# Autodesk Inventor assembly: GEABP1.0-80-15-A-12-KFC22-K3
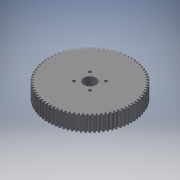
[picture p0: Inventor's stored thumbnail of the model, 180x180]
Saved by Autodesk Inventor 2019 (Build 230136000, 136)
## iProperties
Category: PARTsolutions
Company: MISUMI
Created: 2022-11
Part Number: GEABP1.0-80-15-A-12-KFC22-K3
Catalog Web Link: www.cadenas.de
Description: GEABM, GEABMS, GEABMT, GEABP, GEABPS, GEABPT, GEABA, GEABAS, GEABAT-Plastic Spur Gears - Pressure Angle 20 Degrees, Module 0.5/0.8/1.0/1.5/2.0/2.5/3.0
Vendor: MISUMI
Document SubType Name: Assembly
Designer: psAdmin
Manufacturer: MISUMI
Mass: 72.9245 g
Surface Area: 182.111 cm^2
Volume: 72.9245 cm^3
Density: 1 g/cm^3
Title: GEABP1.0-80-15-A-12-KFC22-K3
Author: Cadenas PARTsolutions
Comments: Plastic Spur Gears - Pressure Angle 20 Degrees, Module 0.5/0.8/1.0/1.5/2.0/2.5/3.0
PSOL_IDENT_0: {$CADENAS_DATA/23d-libs/misumi/metric/54_spur_gears/geabms20_asmtab.prj},415 {VTYP=3D},{STYP=ASSTAB}
PSOL_IDENT_1: ,{NB=GEABP1.0-80-15-A-12-KFC22-K3},{LINA=GEABP1.0-80-15-A-12-KFC22-K3},{NN=GEABM, GEABMS, GEABMT, GE
PSOL_IDENT_2: ABP, GEABPS, GEABPT, GEABA, GEABAS, GEABAT},{DATE=16.08.2021 10:08:31},{GEOMDATE=16.08.2021 10:08:28
PSOL_IDENT_3: },{VERSION=},{LINEID=30},{WBVAR=MATSG,MATCR,NT,B,TS,PS,ALT1,ALT2,TPC,ALT11,ALT10,BS,ALT3,Z,J,ALT4,Q,
PSOL_IDENT_4: R,S,T,ALT5,LFC,LTC,MALT5,ALT6,KFC,KTC,K},{WBNUMERIC=NT,B,BS,Z,J,Q,R,S,T,LFC,LTC,KFC,KTC,K}  {NB=GEAB
PSOL_IDENT_5: P1.0-80-15-A-12-KFC22-K3},{LINA=GEABP1.0-80-15-A-12-KFC22-K3},{KT=DUMMY},{PN=GEABP1.0-80-15-A-12-KFC
PSOL_IDENT_6: 22-K3},{TYPE=GEABP},{MATSG=PW},{MATSGALG='MCN','MC Nylon','PW','Polyacetal White','PB','Polyacetal B
PSOL_IDENT_7: lue'},{MATCR=},{MATCRALG='','-','S45C','1045 Carbon Steel','SUS304','304 Stainless Steel'},{MOD=1.0}
PSOL_IDENT_8: ,{MOD1=1.0},{NT=80},{NTALG=15,16,18,20,22,24,25,26,28,30,32,35,36,40,45,48,50,55,60,70,75,80,90,100,
PSOL_IDENT_9: 120},{B=15},{BALG=10,15},{TS=A},{TSALG='A','A','B','B'},{TSPN=-A},{PS=12},{PSALG='10','10','11','11'
PSOL_IDENT_10: ,'12','12','13','13','14','14','15','15','16','16','17','17','18','18','19','19','20','20','21','21'
PSOL_IDENT_11: ,'22','22','23','23','24','24','25','25','26','26','27','27','28','28'},{PSCRL='10','10','11','11','
PSOL_IDENT_12: 12','12','13','13','14','14','15','15','16','16','17','17','18','18','19','19','20','20','21','21','
PSOL_IDENT_13: 22','22','23','23','24','24','25','25','26','26','27','27','28','28'},{PSCRW='10','10','12','12','15'
PSOL_IDENT_14: ,'15','20','20'},{DD=80.0},{DD05=40},{DD08=64},{DD10=80},{DD15=120},{DD20=0},{DD25=0},{DD30=0},{D=82
PSOL_IDENT_15: .0},{D05=41},{D08=65.6},{D10=82},{D15=123},{D20=0},{D25=0},{D30=0},{G=77.50},{G05=38.75},{G08=62},{G
PSOL_IDENT_16: 10=77.5},{G15=116.25},{G20=0},{G25=0},{G30=0},{H=0.0},{L=0},{LL1=0},{LL2=0.0},{M=-},{M3D=0},{P=12.00
PSOL_IDENT_17: },{DD1=0},{CIFR=15},{CIFM=0},{CIFK=0},{CIFTAP=0},{SCREW=0.000},{SCREWL=0.000},{ALT1=},{ALT1ALG='','N
PSOL_IDENT_18: ot applicable'},{ALT1PN=},{ALT2=},{ALT2ALG='','Not applicable'},{TPC=N/A},{TPCALG='N/A'},{ALT2PN=},{
PSOL_IDENT_19: KC=0},{ALT11=},{ALT11ALG='','Not applicable'},{ALT11PN=},{DEG=0},{ALT10=},{ALT10ALG= '','Not applica
PSOL_IDENT_20: ble' },{ALT10PN=},{BS=0.0},{BSALG=0},{BSMIN=3.000},{BSMINALG=3},{BSMAX=0},{LL13D=0},{LL23D=0},{ALT3=
PSOL_IDENT_21: },{ALT3ALG= '','w/o Stepped Hole','DHL','with DHL (Stepped Hole)','DHR','with DHR (Stepped Hole)' },
PSOL_IDENT_22: {ALT3PN=},{ZJPN=},{ALT31=1},{ALT32=1},{Z=0},{ZALG=0},{ZMINL=14},{ZMAXL=73},{ZMINR=14},{ZMAXR=73},{ZP
PSOL_IDENT_23: N=},{J=0.0},{JALG=0},{JMIN=2},{JMAX=0},{JPN=},{ALT4=},{ALT4ALG= '','w/o WDH (Both Ends Stepped Hole)'
PSOL_IDENT_24: ,'WDH','with WDH (Both Ends Stepped Hole)' },{ALT4PN=},{QRSTPN=},{LB=15.000},{Q=0},{QALG=0},{QMIN=14
PSOL_IDENT_25: },{QMAX=73},{QPN=},{R=0},{RALG=0},{RMIN=14},{RMAX=73},{RPN=},{S=0},{SALG=0},{SMIN=3},{SMAX=9},{SPN=}
PSOL_IDENT_26: ,{T=0},{TALG=0},{TMIN=3},{TMAX=0},{TPN=},{ALT5=},{ALT5ALG= '','w/o Side Slotted Hole','LFC','with LF
PSOL_IDENT_27: C (Side Slotted Hole)','LTC','with LTC (Side Slotted Hole)' },{LFC=0},{LFCALG=0},{LTC=0},{LTCALG=0},
PSOL_IDENT_28: {LPCDMIN=20},{LPCDMAX=70},{LCMAX=73},{MALT5=N/A},{MALT5ALG= 'N/A' },{LCMAX2=70},{C=0.0},{ALT5PN=},{A
PSOL_IDENT_29: LT6=KFC},{ALT6ALG= '','w/o Side Through Hole','KFC','with KFC (Side Through Hole)','KTC','with KTC (
PSOL_IDENT_30: Side Through Hole)' },{ALT6PN=-KFC},{KFTCPN=22-K3},{KFC=22},{KFCALG=[19:70/1]},{KFCPN=22},{KTC=0},{K
PSOL_IDENT_31: TCALG=[0]},{KTCPN=},{KPCDMIN1=19},{KPCDMAX1=-7},{KPCDMIN2=7},{KPCDMAX2=70},{K=3.0},{KALG=[3:6/0.5]},
PSOL_IDENT_32: {KPCD=22},{KPN=-K3},{AG=0},{LBS=15},{PCD=22},{SHN=4},{SHDEG1=45},{SHDEG2=90},{PZQRDD2=12},{PPATH=gea
PSOL_IDENT_33: bms20/geabms20_asmtpl.prj}
NB: GEABP1.0-80-15-A-12-KFC22-K3
NN: GEABM, GEABMS, GEABMT, GEABP, GEABPS, GEABPT, GEABA, GEABAS, GEABAT
NT: 80
NBSYN: $PN.
LINA: GEABP1.0-80-15-A-12-KFC22-K3
CATALOG: Misumi
PN: GEABP1.0-80-15-A-12-KFC22-K3
MATSG: Polyacetal White
MATCR: -
MOD: 1.0
B: 15
TS: A
PS: 12
DD: 80
D: 82
G: 77.5
H: 0
L: 0
LL1: 0
LL2: 0
M: -
DD1: 0
ALT1: Not applicable
ALT2: Not applicable
TPC: N/A
ALT11: Not applicable
ALT10: Not applicable
BS: 0
ALT3: w/o Stepped Hole
Z: 0
J: 0
ALT4: w/o WDH (Both Ends Stepped Hole)
Q: 0
R: 0
S: 0
T: 0
ALT5: w/o Side Slotted Hole
LFC: 0
LTC: 0
MALT5: N/A
C: 0
ALT6: with KFC (Side Through Hole)
KFC: 22
KTC: 0
K: 3
SUPPLIER: MISUMI
ARTICLENO: GEABP1.0-80-15-A-12-KFC22-K3
BOMINFO: GEABP1.0-80-15-A-12-KFC22-K3
CREATOR: CADENAS GmbH
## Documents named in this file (2)
- e:\temp\worker_COMMON_2\temp\tmp_7296_40_FNSQH\format_0\GEABP1_0-80-15-A-12-KFC22-K3.iam
- e:\temp\worker_COMMON_2\temp\tmp_7296_40_FNSQH\format_0\GEABP1_0-80-15-A-12-KFC22-K3_b.ipt
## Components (1 placed, 1 different names)
1. GEABP1_0-80-15-A-12-KFC22-K3_b:1
